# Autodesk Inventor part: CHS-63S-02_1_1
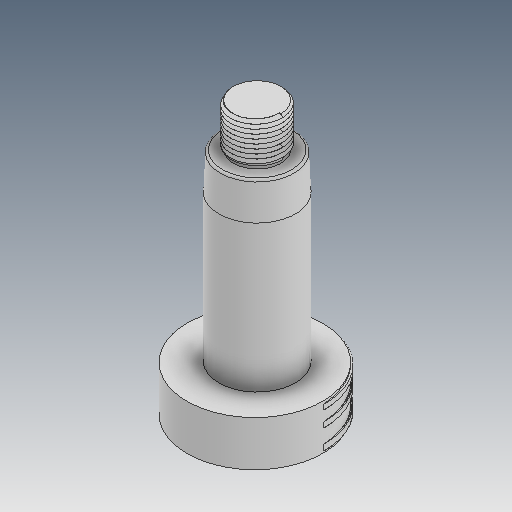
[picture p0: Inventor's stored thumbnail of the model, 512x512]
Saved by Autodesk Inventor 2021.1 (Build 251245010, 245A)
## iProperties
Created: 2019-05
Part Number: CHS-63S-02_1_1
Material: Ogólny
Document SubType Name: Modeling
Designer: user
Density: 1 g/cm^3
Appearance: Domyślna
Author: user
Revision Number: ÈÎºÎ
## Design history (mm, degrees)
feature "ÊäÈë1"
feature "ÊäÈë2"
node "Bryła1"
node "Bryła2"
